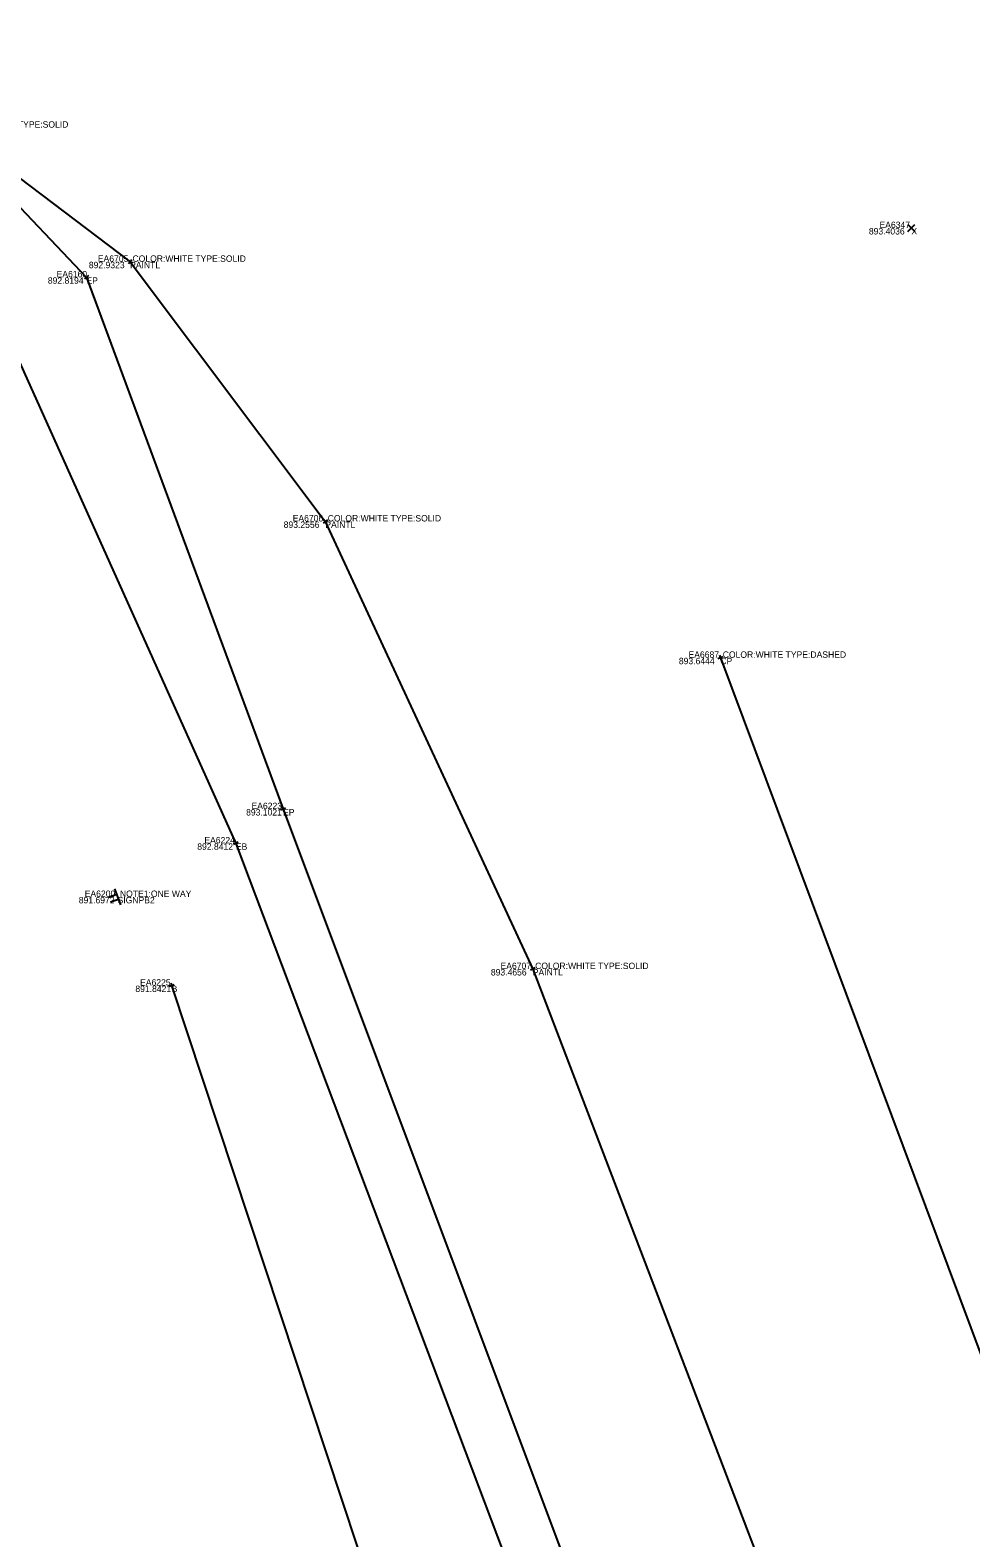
# Model space of a CAD drawing. Extents: x 179049 to 189691, y 286531 to 301260.
# Drawn here: x 180214.4 to 180258.4, y 300511.9 to 300582.5 of the extents above; entities that cross this region are included whole.
import ezdxf

# ---------------------------------------------------------------- set-up
doc = ezdxf.new("R2010")
doc.units = 0
for name, color, linetype in [('PM_X_Channelizing_Line', 7, 'Continuous'), ('PV_X_COP', 7, 'Continuous'), ('PV_X_EOP', 7, 'Continuous'), ('PV_X_Shoulder_Aggregate', 7, 'Continuous'), ('SN_X_Public', 7, 'Continuous'), ('SV_X_Break_Lines', 7, 'Continuous'), ('SV_X_Random_Point', 7, 'Continuous'), ('SV_X_Shot_Marker', 7, 'Continuous'), ('SV_X_Text_Comment', 7, 'Continuous'), ('SV_X_Text_Description', 7, 'Continuous'), ('SV_X_Text_Elevation', 7, 'Continuous'), ('SV_X_Text_Name', 7, 'Continuous')]:
    doc.layers.add(name, color=color, linetype=linetype)

msp = doc.modelspace()

# ---------------------------------------------------------------- linework, layer by layer
at = {"layer": 'PM_X_Channelizing_Line'}
msp.add_lwpolyline([(180190.445, 300582.496), (180201.741, 300580.903), (180210.797, 300577.931), (180219.101, 300571.651), (180228.235, 300559.496), (180237.94, 300538.543), (180264.924, 300467.918), (180293.4, 300391.707), (180324.643, 300308.043), (180350.475, 300238.896)], dxfattribs=at)
at = {"layer": 'PV_X_COP'}
msp.add_lwpolyline([(180246.716, 300553.114), (180279.248, 300465.999), (180313.722, 300372.324), (180349.437, 300276.58), (180362.146, 300242.511)], dxfattribs=at)
at = {"layer": 'PV_X_EOP'}
msp.add_lwpolyline([(179371.146, 300578.051), (179477.168, 300579.528), (179563.012, 300579.455), (179660.626, 300579.907), (179772.349, 300580.843), (179883.302, 300581.216), (179986.953, 300581.659), (180080.461, 300581.624), (180131.142, 300581.875), (180152.421, 300580.897), (180177.372, 300581.245), (180192.481, 300580.813), (180205.116, 300578.916), (180211.895, 300576.366), (180217.061, 300570.924), (180226.256, 300546.032), (180252.64, 300475.662), (180284.891, 300388.784), (180312.046, 300315.753), (180341.998, 300235.308)], dxfattribs=at)
at = {"layer": 'PV_X_Shoulder_Aggregate'}
msp.add_lwpolyline([(179563.451, 300578.229), (179660.977, 300578.016), (179772.748, 300578.901), (179883.7, 300579.446), (179986.895, 300579.719), (180080.262, 300579.655), (180131.517, 300579.632), (180152.892, 300578.404), (180177.169, 300578.87), (180192.854, 300577.824), (180203.732, 300575.396), (180212.869, 300569.272), (180224.05, 300544.426), (180250.422, 300474.503), (180282.665, 300386.992), (180309.922, 300313.986), (180339.844, 300234.334)], dxfattribs=at)
at = {"layer": 'SN_X_Public'}
for p, q in [((180218.473, 300542.033), (180218.097, 300541.896)), ((180218.377, 300542.296), (180218.651, 300541.544)), ((180218.514, 300541.92), (180218.514, 300541.92)), ((180218.555, 300541.807), (180218.179, 300541.671))]:
    msp.add_line(p, q, dxfattribs=at)
at = {"layer": 'SV_X_Break_Lines'}
msp.add_lwpolyline([(180221.044, 300537.77), (180244.232, 300467.66), (180276.377, 300381.787), (180302.554, 300313.637), (180332.865, 300230.917)], dxfattribs=at)
at = {"layer": 'SV_X_Random_Point'}
for p, q in [((180255.488, 300573.064), (180255.821, 300573.398)), ((180255.488, 300573.398), (180255.821, 300573.064))]:
    msp.add_line(p, q, dxfattribs=at)
at = {"layer": 'SV_X_Shot_Marker'}
for p, q in [((180219.001, 300571.726), (180219.201, 300571.575)), ((180219.176, 300571.75), (180219.025, 300571.551)), ((180219.101, 300571.651), (180219.101, 300571.651)), ((180217.151, 300571.01), (180216.97, 300570.838)), ((180216.975, 300571.015), (180217.147, 300570.834)), ((180217.061, 300570.924), (180217.061, 300570.924)), ((180228.335, 300559.571), (180228.135, 300559.421)), ((180228.16, 300559.596), (180228.31, 300559.396)), ((180228.235, 300559.496), (180228.235, 300559.496)), ((180246.672, 300553.231), (180246.76, 300552.997)), ((180246.833, 300553.158), (180246.599, 300553.07)), ((180246.716, 300553.114), (180246.716, 300553.114)), ((180226.213, 300546.15), (180226.299, 300545.915)), ((180226.373, 300546.076), (180226.139, 300545.989)), ((180226.256, 300546.032), (180226.256, 300546.032)), ((180224.164, 300544.477), (180223.936, 300544.375)), ((180223.999, 300544.54), (180224.101, 300544.312)), ((180224.05, 300544.426), (180224.05, 300544.426)), ((180238.054, 300538.596), (180237.827, 300538.491)), ((180237.888, 300538.657), (180237.993, 300538.43)), ((180237.94, 300538.543), (180237.94, 300538.543)), ((180221.163, 300537.809), (180220.926, 300537.731)), ((180221.005, 300537.889), (180221.084, 300537.651)), ((180221.044, 300537.77), (180221.044, 300537.77))]:
    msp.add_line(p, q, dxfattribs=at)

# ---------------------------------------------------------------- texts
at = {"layer": 'SV_X_Text_Comment'}
for s, p in [('X', (180255.654, 300572.931)), ('PAINTL', (180219.101, 300571.351)), ('EP', (180217.061, 300570.624)), ('PAINTL', (180228.235, 300559.196)), ('CP', (180246.716, 300552.814)), ('EP', (180226.256, 300545.732)), ('EB', (180224.05, 300544.126)), ('SIGNPB2', (180218.514, 300541.62)), ('PAINTL', (180237.94, 300538.243)), ('B', (180221.044, 300537.47))]:
    msp.add_text(s, height=0.3, dxfattribs=at).set_placement(p)
at = {"layer": 'SV_X_Text_Description'}
for s, p in [(' COLOR:WHITE TYPE:SOLID', (180210.797, 300577.931)), (' COLOR:WHITE TYPE:SOLID', (180219.101, 300571.651)), (' COLOR:WHITE TYPE:SOLID', (180228.235, 300559.496)), (' COLOR:WHITE TYPE:DASHED', (180246.716, 300553.114)), (' NOTE1:ONE WAY', (180218.514, 300541.92)), (' COLOR:WHITE TYPE:SOLID', (180237.94, 300538.543))]:
    msp.add_text(s, height=0.3, dxfattribs=at).set_placement(p)
at = {"layer": 'SV_X_Text_Elevation'}
for s, p in [('893.4036', (180253.666, 300572.931)), ('892.9323', (180217.171, 300571.351)), ('892.8194', (180215.252, 300570.624)), ('893.2556', (180226.287, 300559.196)), ('893.6444', (180244.775, 300552.814)), ('893.1021', (180224.529, 300545.732)), ('892.8412', (180222.243, 300544.126)), ('891.6972', (180216.7, 300541.62)), ('893.4656', (180235.98, 300538.243)), ('891.8421', (180219.348, 300537.47))]:
    msp.add_text(s, height=0.3, dxfattribs=at).set_placement(p)
at = {"layer": 'SV_X_Text_Name'}
for s, p in [('EA6347', (180254.162, 300573.231)), ('EA6705', (180217.592, 300571.651)), ('EA6160', (180215.663, 300570.924)), ('EA6706', (180226.707, 300559.496)), ('EA6687', (180245.226, 300553.114)), ('EA6223', (180224.78, 300546.032)), ('EA6224', (180222.576, 300544.426)), ('EA6200', (180216.978, 300541.92)), ('EA6707', (180236.431, 300538.543)), ('EA6225', (180219.568, 300537.77))]:
    msp.add_text(s, height=0.3, dxfattribs=at).set_placement(p)

doc.saveas('drawing.dxf')
